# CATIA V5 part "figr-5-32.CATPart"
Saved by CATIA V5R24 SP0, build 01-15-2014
Part number: Part1
Bounding box of the stored display mesh (mm): x -32.491 to 32.491, y -32.393 to 32.393, z 0 to 85.656
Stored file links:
  D:\KAVITA\CATIA V5-6R2014 Project_ Kavita\CATIA V5-6R2014_partfiles\Partfiles\c05_catia_v5-6r2014_prt\figr-5-32.CATPart
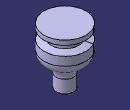
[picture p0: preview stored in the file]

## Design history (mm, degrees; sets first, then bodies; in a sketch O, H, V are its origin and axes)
Body1 (main body)
  Sketch1 on yz-plane, origin (0, 0, 0), H (0, 1, 0), V (0, 0, 1)
    axis line L1 (0, 0) -> (0, 100.0993)
    line L2 (0, 0) -> (13.3295, 0)
    line L3 (13.3295, 0) -> (13.3295, 19.6564)
    arc A1 centre (31.7623, 19.6564) radius 18.4328 from (13.3295, 19.6564) to (23.518, 36.1427) cw
    arc A2 centre (16.25, 50.6768) radius 16.25 from (23.518, 36.1427) to (32.5, 50.6768) ccw
    line L4 (32.5, 50.6768) -> (32.5, 85.6563)
    line L5 (32.5, 85.6563) -> (0, 85.6563)
    point P9 (0, 85.6563)
    line L6 (0, 85.6563) -> (0, 0)
    radius about axis L4 L1 = 32.5
    vertical: L1 V, L3 V, L4 V
    horizontal: L2 H, L5 H
    tangency: A1 L3, A2 L1, A2 A1, L4 A2, L6 A2
    coincidence: P9 L1
  Shaft1: profile Sketch1, axis Sketch1.L1, angle 360
  Sketch2 on yz-plane, origin (0, 0, 0), H (0, 1, 0), V (0, 0, 1)
    axis line L1 (0, 0) -> (0, 91.1904)
    point P1 (0, 0)
    point P2 (0, 91.1904)
    line L2 (32.5, 78.7512) -> (21.4593, 75.7196)
    line L3 (21.4593, 75.7196) -> (21.4593, 66.4534)
    line L4 (21.4593, 66.4534) -> (32.5, 63.9927)
    line L5 (32.5, 63.9927) -> (32.5, 78.7512)
    coincidence: P1 H, P2 V
    vertical: L1 V, L3 V, L5 V
  Groove1: profile Sketch2, axis Sketch2.L1, angle 360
